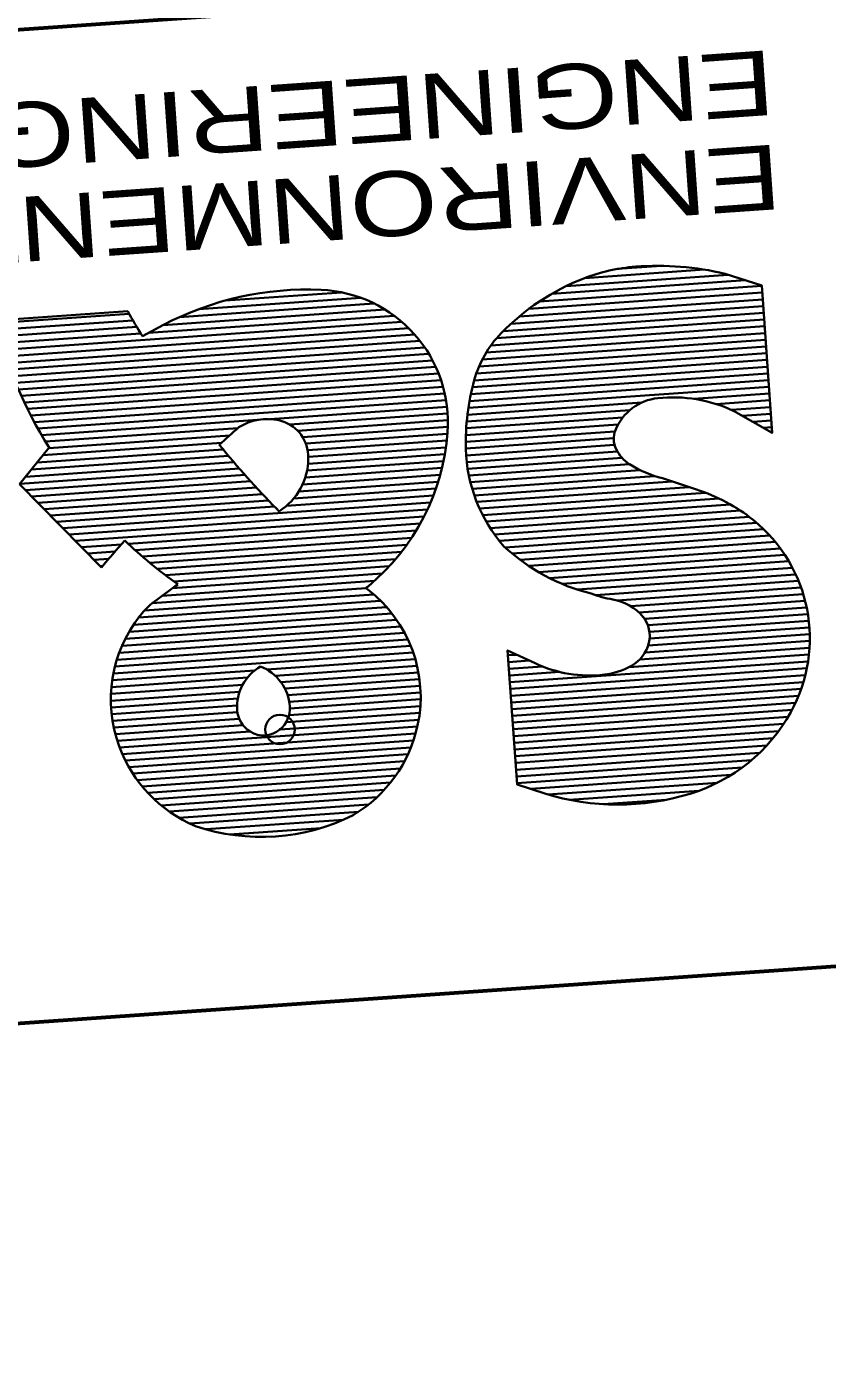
# Model space of a CAD drawing. Extents: x 2399800 to 2400616, y 567351 to 568869.
# Drawn here: x 2400147.4 to 2400180, y 568757 to 568811.7 of the extents above; entities that cross this region are included whole.
import ezdxf

# ---------------------------------------------------------------- set-up
doc = ezdxf.new("R2010")
doc.units = 0
doc.header["$LTSCALE"] = 2.4
doc.header["$PDMODE"] = 32
doc.header["$PDSIZE"] = 1.2
doc.layers.add('63', color=7, linetype='Continuous', lineweight=35)

msp = doc.modelspace()

# ---------------------------------------------------------------- linework, layer by layer
at = {"layer": '63'}
for p, q in [((2400442.155, 568832.216), (2399943.373, 568797.338)), ((2400173.245, 568801.939), (2400171.436, 568801.813)), ((2400175.962, 568801.578), (2400169.366, 568801.117)), ((2400174.995, 568801.786), (2400170.119, 568801.445)), ((2400160.214, 568800.861), (2400155.486, 568800.53)), ((2400177.349, 568800.848), (2400167.838, 568800.183)), ((2400177.33, 568801.122), (2400168.271, 568800.489)), ((2400176.663, 568801.351), (2400168.771, 568800.799)), ((2400161.546, 568800.402), (2400153.598, 568799.846)), ((2400160.995, 568800.639), (2400154.399, 568800.178)), ((2400177.387, 568800.299), (2400167.112, 568799.581)), ((2400177.368, 568800.574), (2400167.455, 568799.88)), ((2400151.499, 568800.091), (2400146.049, 568799.709)), ((2400151.562, 568799.98), (2400146.079, 568799.596)), ((2400162.354, 568799.907), (2400152.35, 568799.208)), ((2400161.985, 568800.157), (2400152.943, 568799.525)), ((2400177.426, 568799.75), (2400166.527, 568798.988)), ((2400177.407, 568800.025), (2400166.802, 568799.283)), ((2400151.715, 568799.715), (2400146.157, 568799.326)), ((2400151.871, 568799.45), (2400146.238, 568799.056)), ((2400152.029, 568799.185), (2400146.323, 568798.787)), ((2400162.671, 568799.654), (2400146.413, 568798.517)), ((2400162.947, 568799.397), (2400146.507, 568798.248)), ((2400152.955, 568799.532), (2400152.097, 568799.073)), ((2400177.464, 568799.202), (2400166.105, 568798.407)), ((2400177.445, 568799.476), (2400166.297, 568798.696)), ((2400163.191, 568799.139), (2400146.605, 568797.979)), ((2400163.407, 568798.878), (2400146.708, 568797.711)), ((2400177.502, 568798.653), (2400165.811, 568797.836)), ((2400177.483, 568798.927), (2400165.945, 568798.12)), ((2400163.598, 568798.616), (2400146.815, 568797.443)), ((2400163.768, 568798.352), (2400146.927, 568797.174)), ((2400163.918, 568798.087), (2400147.043, 568796.907)), ((2400177.541, 568798.105), (2400165.615, 568797.27)), ((2400177.521, 568798.379), (2400165.702, 568797.552)), ((2400164.05, 568797.821), (2400147.164, 568796.64)), ((2400164.164, 568797.553), (2400147.29, 568796.373)), ((2400177.579, 568797.556), (2400165.478, 568796.709)), ((2400177.56, 568797.83), (2400165.542, 568796.99)), ((2400164.263, 568797.284), (2400147.42, 568796.106)), ((2400164.346, 568797.014), (2400147.556, 568795.84)), ((2400177.618, 568797.007), (2400165.377, 568796.151)), ((2400177.598, 568797.282), (2400165.423, 568796.43)), ((2400164.414, 568796.743), (2400147.697, 568795.574)), ((2400164.468, 568796.471), (2400147.842, 568795.309)), ((2400177.637, 568796.733), (2400174.559, 568796.518)), ((2400177.656, 568796.459), (2400175.476, 568796.306)), ((2400164.507, 568796.199), (2400157.286, 568795.694)), ((2400164.533, 568795.925), (2400158.098, 568795.475)), ((2400171.956, 568796.06), (2400165.309, 568795.595)), ((2400172.442, 568796.37), (2400165.339, 568795.873)), ((2400177.675, 568796.184), (2400176.089, 568796.073)), ((2400177.694, 568795.91), (2400176.533, 568795.829)), ((2400156.791, 568795.659), (2400147.993, 568795.044)), ((2400164.545, 568795.65), (2400158.422, 568795.222)), ((2400164.542, 568795.374), (2400158.627, 568794.96)), ((2400171.478, 568795.475), (2400165.275, 568795.042)), ((2400171.67, 568795.764), (2400165.288, 568795.318)), ((2400177.714, 568795.635), (2400176.961, 568795.583)), ((2400177.732, 568795.361), (2400177.39, 568795.337)), ((2400155.988, 568795.327), (2400148.149, 568794.779)), ((2400155.653, 568795.028), (2400148.281, 568794.512)), ((2400164.526, 568795.097), (2400158.757, 568794.694)), ((2400164.499, 568794.819), (2400158.831, 568794.423)), ((2400171.348, 568795.191), (2400165.269, 568794.765)), ((2400171.299, 568794.911), (2400165.272, 568794.49)), ((2400148.299, 568794.535), (2400147.09, 568793.04)), ((2400155.386, 568794.458), (2400147.808, 568793.928)), ((2400155.323, 568794.729), (2400148.044, 568794.22)), ((2400164.419, 568794.263), (2400158.845, 568793.873)), ((2400164.464, 568794.542), (2400158.855, 568794.149)), ((2400171.331, 568794.638), (2400165.285, 568794.215)), ((2400171.447, 568794.37), (2400165.309, 568793.941)), ((2400155.825, 568793.938), (2400147.336, 568793.344)), ((2400155.604, 568794.198), (2400147.572, 568793.636)), ((2400164.302, 568793.703), (2400158.731, 568793.314)), ((2400164.365, 568793.983), (2400158.805, 568793.595)), ((2400171.639, 568794.108), (2400165.346, 568793.668)), ((2400171.943, 568793.853), (2400165.395, 568793.396)), ((2400156.05, 568793.677), (2400147.099, 568793.052)), ((2400156.279, 568793.418), (2400147.334, 568792.792)), ((2400156.512, 568793.159), (2400147.587, 568792.534)), ((2400164.229, 568793.422), (2400158.621, 568793.03)), ((2400172.38, 568793.608), (2400165.456, 568793.124)), ((2400172.961, 568793.373), (2400165.53, 568792.854)), ((2400173.291, 568793.28), (2400174.666, 568792.821)), ((2400147.09, 568793.04), (2400150.428, 568789.646)), ((2400156.749, 568792.899), (2400147.841, 568792.277)), ((2400156.99, 568792.64), (2400148.095, 568792.019)), ((2400164.054, 568792.859), (2400158.258, 568792.454)), ((2400164.147, 568793.141), (2400158.467, 568792.744)), ((2400173.685, 568793.149), (2400165.617, 568792.584)), ((2400174.368, 568792.921), (2400165.717, 568792.316)), ((2400175.04, 568792.692), (2400165.831, 568792.048)), ((2400157.235, 568792.382), (2400148.349, 568791.76)), ((2400157.484, 568792.124), (2400148.603, 568791.503)), ((2400163.835, 568792.292), (2400148.856, 568791.245)), ((2400163.95, 568792.576), (2400157.968, 568792.157)), ((2400175.595, 568792.455), (2400165.96, 568791.781)), ((2400176.059, 568792.212), (2400166.104, 568791.516)), ((2400163.708, 568792.008), (2400149.11, 568790.987)), ((2400163.569, 568791.722), (2400149.363, 568790.729)), ((2400157.672, 568791.932), (2400157.807, 568792.029)), ((2400176.459, 568791.964), (2400166.265, 568791.251)), ((2400176.812, 568791.713), (2400166.444, 568790.988)), ((2400163.416, 568791.436), (2400151.527, 568790.605)), ((2400163.249, 568791.149), (2400151.807, 568790.348)), ((2400177.127, 568791.459), (2400166.642, 568790.726)), ((2400177.407, 568791.203), (2400166.87, 568790.466)), ((2400151.241, 568790.584), (2400149.617, 568790.471)), ((2400163.067, 568790.86), (2400152.096, 568790.093)), ((2400162.868, 568790.571), (2400152.397, 568789.838)), ((2400177.658, 568790.945), (2400167.161, 568790.211)), ((2400177.882, 568790.685), (2400167.48, 568789.958)), ((2400178.085, 568790.424), (2400167.833, 568789.707)), ((2400150.982, 568790.291), (2400149.871, 568790.213)), ((2400150.728, 568789.997), (2400150.125, 568789.955)), ((2400162.651, 568790.28), (2400152.711, 568789.584)), ((2400162.414, 568789.987), (2400153.036, 568789.331)), ((2400178.268, 568790.161), (2400168.227, 568789.459)), ((2400178.432, 568789.897), (2400168.674, 568789.214)), ((2400150.478, 568789.704), (2400150.379, 568789.697)), ((2400161.867, 568789.398), (2400153.327, 568788.801)), ((2400162.154, 568789.694), (2400153.375, 568789.08)), ((2400178.579, 568789.631), (2400169.191, 568788.975)), ((2400178.711, 568789.365), (2400169.815, 568788.743)), ((2400161.207, 568788.8), (2400152.501, 568788.191)), ((2400161.551, 568789.1), (2400152.907, 568788.495)), ((2400178.827, 568789.097), (2400170.554, 568788.519)), ((2400178.93, 568788.829), (2400171.44, 568788.305)), ((2400161.8, 568788.291), (2400151.941, 568787.601)), ((2400161.522, 568788.547), (2400152.186, 568787.894)), ((2400179.018, 568788.559), (2400171.993, 568788.068)), ((2400179.094, 568788.289), (2400172.319, 568787.815)), ((2400162.262, 568787.771), (2400151.556, 568787.023)), ((2400162.044, 568788.032), (2400151.735, 568787.311)), ((2400179.157, 568788.018), (2400172.545, 568787.555)), ((2400179.207, 568787.745), (2400172.685, 568787.289)), ((2400162.626, 568787.245), (2400151.268, 568786.451)), ((2400162.454, 568787.509), (2400151.402, 568786.736)), ((2400179.245, 568787.473), (2400172.753, 568787.019)), ((2400179.271, 568787.199), (2400172.758, 568786.743)), ((2400162.912, 568786.714), (2400151.059, 568785.885)), ((2400162.778, 568786.981), (2400151.155, 568786.168)), ((2400179.286, 568786.648), (2400172.573, 568786.179)), ((2400179.284, 568786.924), (2400172.7, 568786.464)), ((2400163.13, 568786.178), (2400150.918, 568785.324)), ((2400163.029, 568786.447), (2400150.981, 568785.604)), ((2400167.35, 568786.089), (2400166.99, 568786.064)), ((2400179.251, 568786.095), (2400171.921, 568785.582)), ((2400179.275, 568786.372), (2400172.352, 568785.888)), ((2400163.216, 568785.909), (2400157.169, 568785.486)), ((2400163.287, 568785.638), (2400157.505, 568785.233)), ((2400167.865, 568785.85), (2400167.009, 568785.79)), ((2400168.396, 568785.611), (2400167.028, 568785.515)), ((2400179.215, 568785.816), (2400167.066, 568784.967)), ((2400179.166, 568785.537), (2400167.086, 568784.693)), ((2400156.376, 568785.155), (2400150.837, 568784.767)), ((2400156.674, 568785.451), (2400150.871, 568785.045)), ((2400163.344, 568785.366), (2400157.736, 568784.974)), ((2400163.387, 568785.093), (2400157.899, 568784.709)), ((2400169.105, 568785.385), (2400167.047, 568785.241)), ((2400179.103, 568785.257), (2400167.105, 568784.418)), ((2400179.026, 568784.976), (2400167.124, 568784.144)), ((2400156.06, 568784.581), (2400150.814, 568784.214)), ((2400156.184, 568784.865), (2400150.819, 568784.49)), ((2400163.416, 568784.82), (2400158.01, 568784.442)), ((2400163.432, 568784.545), (2400158.078, 568784.171)), ((2400178.934, 568784.694), (2400167.143, 568783.87)), ((2400178.827, 568784.411), (2400167.162, 568783.595)), ((2400155.987, 568784.3), (2400150.823, 568783.939)), ((2400155.957, 568784.022), (2400150.846, 568783.665)), ((2400163.422, 568783.993), (2400158.068, 568783.619)), ((2400163.433, 568784.27), (2400158.104, 568783.897)), ((2400178.702, 568784.127), (2400167.181, 568783.321)), ((2400155.97, 568783.748), (2400150.883, 568783.392)), ((2400156.044, 568783.477), (2400150.933, 568783.12)), ((2400163.355, 568783.437), (2400157.704, 568783.042)), ((2400163.396, 568783.716), (2400157.951, 568783.335)), ((2400178.56, 568783.841), (2400167.2, 568783.047)), ((2400178.397, 568783.554), (2400167.22, 568782.772)), ((2400156.199, 568783.212), (2400150.998, 568782.849)), ((2400156.484, 568782.956), (2400151.076, 568782.579)), ((2400163.3, 568783.157), (2400151.17, 568782.309)), ((2400163.229, 568782.877), (2400151.279, 568782.041)), ((2400178.216, 568783.265), (2400167.239, 568782.498)), ((2400178.013, 568782.976), (2400167.258, 568782.223)), ((2400163.142, 568782.595), (2400151.405, 568781.775)), ((2400163.038, 568782.312), (2400151.547, 568781.509)), ((2400177.786, 568782.684), (2400167.277, 568781.949)), ((2400177.53, 568782.39), (2400167.297, 568781.675)), ((2400162.916, 568782.028), (2400151.707, 568781.244)), ((2400162.774, 568781.743), (2400151.888, 568780.981)), ((2400177.242, 568782.095), (2400167.316, 568781.4)), ((2400176.913, 568781.796), (2400167.335, 568781.126)), ((2400162.61, 568781.455), (2400152.09, 568780.72)), ((2400162.422, 568781.167), (2400152.317, 568780.46)), ((2400176.532, 568781.494), (2400167.354, 568780.852)), ((2400176.081, 568781.187), (2400167.919, 568780.616)), ((2400162.204, 568780.875), (2400152.572, 568780.202)), ((2400161.953, 568780.582), (2400152.862, 568779.946)), ((2400175.524, 568780.872), (2400168.62, 568780.389)), ((2400161.661, 568780.286), (2400153.192, 568779.694)), ((2400174.769, 568780.543), (2400169.489, 568780.174)), ((2400173.429, 568780.174), (2400170.879, 568779.996)), ((2400161.315, 568779.986), (2400153.577, 568779.445)), ((2400160.895, 568779.681), (2400154.035, 568779.202)), ((2400160.288, 568779.363), (2400154.681, 568778.971)), ((2400159.367, 568779.023), (2400155.64, 568778.762))]:
    msp.add_line(p, q, dxfattribs=at)
at = {"layer": '63', "lineweight": 60}
msp.add_lwpolyline([(2400444.975, 568791.882), (2399946.193, 568757.004), (2399943.373, 568797.338), (2400442.155, 568832.216)], close=True, dxfattribs=at)
at = {"layer": '63'}
for points in [[(2400175.832, 568801.62), (2400177.329, 568801.136), (2400177.749, 568795.131), (2400176.171, 568796.037)], [(2400168.498, 568780.426), (2400167.358, 568780.8), (2400166.976, 568786.264), (2400168.099, 568785.74)]]:
    msp.add_lwpolyline(points, dxfattribs=at)
for centre, radius, start, end in [((2400172.724, 568794.657), 7.27, 94.1993, 111.379), ((2400173.073, 568789.905), 12.036, 76.7487, 94.1993), ((2400173.543, 568792.565), 9.517, 111.379, 135.8798), ((2400158.809, 568788.398), 12.579, 87.4011, 117.7347), ((2400159.134, 568795.558), 5.412, 355.7064, 87.4011), ((2400185.426, 568819.347), 39.01, 209.5783, 211.3123), ((2400164.772, 568804.775), 19.397, 195.1384, 211.8654), ((2400169.903, 568796.095), 4.447, 135.8797, 164.5346), ((2400174.876, 568794.719), 9.606, 164.5347, 181.3946), ((2400173.315, 568794.461), 2.099, 95.9726, 158.0231), ((2400173.706, 568790.724), 5.856, 65.1167, 95.9726), ((2400192.502, 568754.031), 55.124, 131.4289, 132.5411), ((2400157.191, 568793.503), 2.192, 77.5979, 122.0597), ((2400157.335, 568794.162), 1.518, 3.0797, 77.5979), ((2400155.52, 568795.829), 9.036, 309.6899, 355.7064), ((2400172.261, 568794.886), 0.962, 158.0232, 205.9786), ((2400185.425, 568819.346), 39.01, 219.2858, 224.4366), ((2400171.532, 568794.638), 6.261, 181.3946, 221.2957), ((2400172.748, 568795.123), 1.503, 205.9784, 237.5462), ((2400156.276, 568794.105), 2.58, 306.4215, 3.0798), ((2400174.354, 568797.649), 4.497, 237.5461, 256.3181), ((2400172.555, 568786.101), 7.044, 51.1117, 72.5663), ((2400183.038, 568817.007), 35.667, 224.4374, 224.6688), ((2400173.083, 568786.755), 6.204, 331.0073, 51.1116), ((2400192.505, 568754.027), 55.129, 138.2417, 139.751), ((2400164.772, 568804.775), 19.397, 226.3401, 234.6293), ((2400172.292, 568796.354), 8.004, 226.9428, 256.1712), ((2400656.843, 568094.662), 857.529, 125.93856, 126.00972), ((2400183.045, 568817.013), 35.677, 232.243, 232.411), ((2400047.967, 568936.369), 186.002, 307.501, 307.53621), ((2400154.717, 568785.533), 3.46, 126.0097, 141.7217), ((2400157.917, 568784.37), 5.517, 347.8613, 52.4111), ((2400171.99, 568792.781), 4.498, 249.0169, 260.6887), ((2400170.939, 568786.374), 1.994, 38.8564, 80.6889), ((2400156.331, 568784.259), 5.517, 141.7217, 200.1387), ((2400171.538, 568786.857), 1.226, 346.4517, 38.8564), ((2400171.307, 568786.912), 1.463, 299.0029, 346.4519), ((2400157.859, 568783.962), 1.903, 119.8677, 184.0326), ((2400156.203, 568783.846), 1.903, 3.9675, 68.1324), ((2400170.311, 568790.398), 5.156, 244.5992, 276.7509), ((2400170.565, 568788.251), 2.994, 276.7507, 299.0025), ((2400156.982, 568783.9), 1.122, 309.9107, 3.9675), ((2400157.08, 568783.907), 1.122, 184.0325, 238.0893), ((2400172.335, 568787.169), 7.059, 287.1019, 331.0073), ((2400157.036, 568783.836), 1.038, 238.0893, 309.9107), ((2400157.793, 568784.397), 5.644, 300.8075, 347.8613), ((2400156.45, 568784.303), 5.644, 200.1387, 247.1925), ((2400171.459, 568790.015), 10.036, 252.8372, 287.1019), ((2400156.935, 568787.022), 8.361, 251.3587, 296.6413)]:
    msp.add_arc(centre, radius, start, end, dxfattribs=at)
msp.add_point((2400157.702, 568783.04), dxfattribs=at)

# ---------------------------------------------------------------- texts
at = {"layer": '63', "width": 1.3}
for s, p in [('ENGINEERING  TESTING', (2400177.739, 568810.742)), ('ENVIRONMENTAL SERVICES', (2400178.008, 568806.899))]:
    msp.add_text(s, height=2.64, rotation=184, dxfattribs=at).set_placement(p)

doc.saveas('drawing.dxf')
